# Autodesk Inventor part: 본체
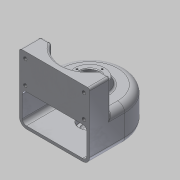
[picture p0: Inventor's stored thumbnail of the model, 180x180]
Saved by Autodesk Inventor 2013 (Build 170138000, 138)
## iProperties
Created: 2015-02
Part Number: 본체
Material: 알루미늄 6061
Document SubType Name: Modeling
Designer: Administrator
Density: 1 g/cm^3
Author: Administrator
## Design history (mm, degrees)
sketch "스케치1"
  geometry: L1 (50, -50)-(-50, -50); L2 (-50, -50)-(-50, 50); L3 (-50, 50)-(50, 50); L4 (50, 50)-(50, -50); L5 (50, -50)-(-50, 50); L6 (-50, -50)-(50, 50); 1 further point
  constraints: 12 end point, 2 midpoint, 2 parallel, 1 horizontal, 1 perpendicular
  dimensions: "d0" = 100 distance of L2.end L3.end; "d1" = 100 distance of L1.end L2.end
extrude "돌출1" new body sketch "스케치1" distance "d2" = 50; taper "d3" = 0 deg
fillet "모깎기1" dims "d4" = 50
feature "쉘1" dims "d5" = 4
sketch "스케치2"
  geometry: L1 (-50, -50)-(50, -50) reference; L2 (50, -50)-(50, 0) reference; L3 (50, -20)-(50, -50); L4 (0, 0)-(0, -65.816); L5 (-50, -20)-(-50, -50); L6 (50, -20)-(34.641, -20); L7 (-50, -20)-(-34.641, -20); L8 (-50, -50)-(50, -50); A1 r 50 centre (0, 0) between (50, 0) and (-50, 0) reference; A2 r 40 centre (0, 0) between (-34.641, -20) and (34.641, -20)
  constraints: 12 end point, 3 collinear, 2 point on circle, 2 symmetric about line, 1 centre point, 1 coincident, 1 parallel, 1 perpendicular, 1 point on line
  dimensions: "d6" = 80 diameter of A2; "d8" = 50 distance between parallel lines of L4 L3; "d9" = 30 distance between parallel lines of L1 L7
extrude "돌출2" join sketch "스케치2" distance "d10" = 45; taper "d11" = 0 deg
sketch "스케치3"
  geometry: C1 r 25 at (0, 0); A1 r 50 centre (0, 0) between (50, 0) and (-50, 0) reference
  constraints: 1 centre point, 1 coincident
  dimensions: "d12" = 50 diameter of C1
extrude "돌출3" join sketch "스케치3" distance "d14" = 10; taper "d15" = 0 deg
sketch "스케치4"
  geometry: C1 r 20 at (0, 0); A1 r 50 centre (0, 0) between (50, 0) and (-50, 0) reference
  constraints: 1 centre point, 1 coincident
  dimensions: "d16" = 40 diameter of C1
extrude "돌출4" join sketch "스케치4" distance "d18" = 9; taper "d19" = 0 deg
feature "면 기울기1" dims angle "d20" = 20 deg
hole "구멍1" diameter "d23" = 28; stored, may be unused: countersink angle "d27" = 90 deg, drill point angle "d29" = 0 deg; dims "d21" = 10, "d22" = 10, "d24" = 6, "d25" = 4, "d26" = 2, "d28" = 10
hole "구멍2" diameter "d32" = 20; stored, may be unused: countersink angle "d36" = 90 deg, drill point angle "d38" = 0 deg; dims "d30" = 10, "d31" = 10, "d33" = 6, "d34" = 4, "d35" = 2, "d37" = 4
hole "구멍3" diameter "d41" = 28; stored, may be unused: countersink angle "d45" = 90 deg, drill point angle "d47" = 0 deg; dims "d39" = 10, "d40" = 10, "d42" = 6, "d43" = 4, "d44" = 2, "d46" = 8
hole "구멍4" diameter "d50" = 20; stored, may be unused: countersink angle "d54" = 90 deg, drill point angle "d56" = 0 deg; dims "d48" = 10, "d49" = 10, "d51" = 6, "d52" = 4, "d53" = 2, "d55" = 2
fillet "모깎기2" dims "d57" = 10
fillet "모깎기3" dims "d58" = 0.3
fillet "모깎기4" dims "d59" = 3
fillet "모깎기5" dims "d60" = 3
chamfer "모따기1" distance "d61" = 1; stored, may be unused: second distance "d62" = 2, angle "d63" = 45 deg
fillet "모깎기6" dims "d64" = 6
sketch "스케치5"
  geometry: L1 (-7, 95)-(87, 95) reference; L2 (-10, 10)-(-10, 92) reference; 2 further points
  dimensions: "d65" = 9 distance from line of L1 point (-1.75, 86); "d66" = 8.25 distance from line of L2 point (-1.75, 86)
hole "구멍5" sketch "스케치5" at (-1.75, 86) diameter "d67" = 5.134; stored, may be unused: countersink angle "d71" = 90 deg, drill point angle "d73" = 118 deg; dims "d68" = 10, "d69" = 4, "d70" = 2, "d72" = 13
sketch "스케치6" dims "d80" = 36
  geometry: C1 r 21.36 at (0, 0) reference; C2 r 15 at (0, 0) reference; 2 further points
  constraints: 2 vertical alignment, 1 coincident, 2 other
hole "구멍6" sketch "스케치6" at (0, 18) diameter "d82" = 2.459; stored, may be unused: countersink angle "d86" = 90 deg, drill point angle "d88" = 118 deg; dims "d83" = 6, "d84" = 4, "d85" = 2, "d87" = 9
node "작업 평면1"
sketch "스케치7"
  geometry: L1 (40, 0)-(-40, 0) reference; 2 further points
  constraints: 1 vertical alignment, 1 other
  dimensions: "d92" = 25 distance from line of L1 point (0, 25)
feature "엠보싱1" sketch "스케치7" dims "d0" = 100, "d1" = 100, "d6" = 80, "d8" = 50, "d9" = 30, "d93" = 1, "d94" = 0
node "솔리드1"
pattern_linear "직사각형 패턴1" dims "d76" = 83.5, "d79" = 33
pattern_circular "원형 패턴1" dims angle "d90" = 360 deg
